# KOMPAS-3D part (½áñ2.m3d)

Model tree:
1. Эскиз:1
2. Операция выдавливания:1
     Расстояние 1 = 20
3. Эскиз:2
4. Операция выдавливания:2
     Расстояние 1 = 400
5. Эскиз:3
6. Вырезать элемент выдавливания:1
     Расстояние 1 = 70
7. Эскиз:4
8. Вырезать элемент выдавливания:2
     Расстояние 1 = 2
9. Эскиз:5
10. Эскиз:6
11. Вырезать элемент выдавливания:3
     Расстояние 2 = 40; Расстояние 1 = 36
12. Эскиз:9
13. Вырезать элемент выдавливания:5
     Расстояние 1 = 40
14. Эскиз:10
15. Вырезать элемент выдавливания:6
     Расстояние 1 = 40
